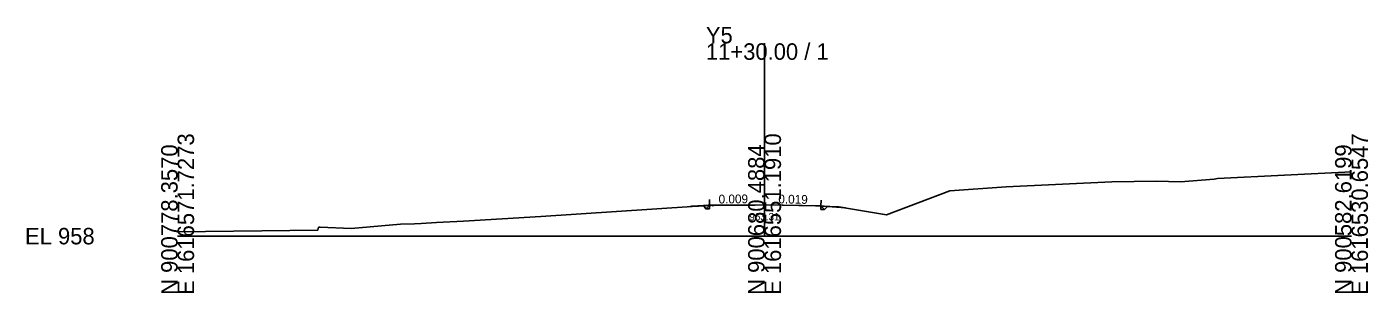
# Model space of a CAD drawing. Extents: x -26 to 1403, y -10 to 4517.
# Drawn here: x 1174.3 to 1402.8, y 490.3 to 535.6 of the extents above; entities that cross this region are included whole.
import ezdxf

# ---------------------------------------------------------------- set-up
doc = ezdxf.new("R2010")
doc.units = 0
for name, color, linetype in [('Exist Cross Section Cell', 7, 'Continuous'), ('Exist XS Center Line Elevation Label', 7, 'Continuous'), ('Exist XS Ground Line', 7, 'Continuous'), ('Prop XS Dump Level', 7, 'Continuous'), ('Prop XS Earthwork Shape', 7, 'Continuous'), ('Prop XS EOT Tick Mark', 7, 'Continuous'), ('Prop XS Finish Grade', 7, 'Continuous'), ('Prop XS Finish Grade Earthwork', 7, 'Continuous'), ('Prop XS Finish Grade Pavement', 7, 'Continuous'), ('Prop XS Pvmt Edge Slope', 7, 'Continuous'), ('Prop XS Subgrade Earthwork', 7, 'Continuous')]:
    doc.layers.add(name, color=color, linetype=linetype)

msp = doc.modelspace()

# ---------------------------------------------------------------- linework, layer by layer
at = {"layer": 'Exist Cross Section Cell'}
for p, q in [((1300, 500), (1300, 532.79)), ((1200, 500), (1300, 500)), ((1300, 500), (1400, 500))]:
    msp.add_line(p, q, dxfattribs=at)
at = {"layer": 'Exist XS Ground Line'}
for p, q in [((1370.85, 509.25), (1376.62, 509.67)), ((1376.62, 509.67), (1377.16, 509.8)), ((1377.16, 509.8), (1400, 510.93)), ((1320.75, 503.6), (1331.54, 507.68)), ((1331.54, 507.68), (1341.18, 508.38)), ((1341.18, 508.38), (1359.14, 509.23)), ((1359.14, 509.23), (1366.75, 509.32)), ((1366.75, 509.32), (1370.85, 509.25)), ((1287.69, 505.02), (1288.72, 505.07)), ((1288.72, 505.07), (1290.43, 505.24)), ((1290.43, 505.24), (1298.4, 505.27)), ((1298.4, 505.27), (1300.18, 505.32)), ((1300.18, 505.32), (1308.68, 505.16)), ((1308.68, 505.16), (1309.34, 505.14)), ((1309.34, 505.14), (1309.72, 505.12)), ((1309.72, 505.12), (1312.61, 505.01)), ((1248.72, 502.57), (1261.89, 503.35)), ((1261.89, 503.35), (1287.69, 505.02)), ((1312.61, 505.01), (1320.75, 503.6)), ((1200, 500.74), (1223.87, 500.99)), ((1223.87, 500.99), (1223.98, 501.51)), ((1223.98, 501.51), (1224.31, 501.5)), ((1224.31, 501.5), (1229.56, 501.32)), ((1229.56, 501.32), (1237.95, 502.02)), ((1237.95, 502.02), (1240.36, 502.07)), ((1240.36, 502.07), (1241.48, 502.15)), ((1241.48, 502.15), (1244.13, 502.34)), ((1244.13, 502.34), (1248.72, 502.57))]:
    msp.add_line(p, q, dxfattribs=at)
at = {"layer": 'Prop XS Dump Level'}
for p, q in [((1290.61, 505.23), (1300, 505.31)), ((1300, 505.31), (1309.61, 505.13))]:
    msp.add_line(p, q, dxfattribs=at)
at = {"layer": 'Prop XS Earthwork Shape'}
for points in [[(1287.04, 504.98), (1287.69, 505.02), (1288.72, 505.07), (1289.63, 505.16), (1289.61, 505.2), (1287.6, 505.12)], [(1290.61, 505.23), (1290.27, 505.22), (1289.63, 505.16), (1290.01, 504.63)], [(1290.61, 504.65), (1290.01, 504.63), (1290.61, 505.23)], [(1290.61, 505.23), (1290.27, 505.22), (1290.43, 505.24)], [(1309.61, 505.13), (1310.19, 504.55), (1310.71, 505.04)], [(1309.61, 505.13), (1310.19, 504.55), (1309.61, 504.55)], [(1309.61, 505.13), (1309.72, 505.12), (1312.61, 505.01), (1313.8, 504.8), (1310.71, 505.04)]]:
    msp.add_lwpolyline(points, close=True, dxfattribs=at)
at = {"layer": 'Prop XS EOT Tick Mark'}
for p, q in [((1290.61, 505.23), (1290.61, 506.23)), ((1309.61, 505.13), (1309.63, 506.13))]:
    msp.add_line(p, q, dxfattribs=at)
at = {"layer": 'Prop XS Finish Grade'}
for p, q in [((1290.61, 505.23), (1289.61, 505.2)), ((1309.61, 505.13), (1310.71, 505.04))]:
    msp.add_line(p, q, dxfattribs=at)
at = {"layer": 'Prop XS Finish Grade Earthwork'}
for p, q in [((1287.6, 505.12), (1287.04, 504.98)), ((1289.61, 505.19), (1287.6, 505.12)), ((1310.71, 505.04), (1313.8, 504.8))]:
    msp.add_line(p, q, dxfattribs=at)
at = {"layer": 'Prop XS Finish Grade Pavement'}
for p, q in [((1290.61, 505.23), (1300, 505.31)), ((1300, 505.31), (1309.61, 505.13))]:
    msp.add_line(p, q, dxfattribs=at)
at = {"layer": 'Prop XS Pvmt Edge Slope'}
for p, q in [((1290.61, 505.23), (1290.01, 504.63)), ((1309.61, 505.13), (1310.19, 504.55))]:
    msp.add_line(p, q, dxfattribs=at)
at = {"layer": 'Prop XS Subgrade Earthwork'}
for p, q in [((1290.01, 504.63), (1289.61, 505.2)), ((1290.61, 504.65), (1290.61, 505.24)), ((1309.61, 504.55), (1309.61, 505.13)), ((1290.61, 504.65), (1290.01, 504.63)), ((1309.61, 504.55), (1310.19, 504.55)), ((1310.71, 505.04), (1310.19, 504.55))]:
    msp.add_line(p, q, dxfattribs=at)

# ---------------------------------------------------------------- texts
at = {"layer": 'Exist Cross Section Cell'}
for s, p in [('Y5', (1290, 532.79)), ('11+30.00 / 1', (1290, 529.99)), ('EL 958', (1174, 498.6))]:
    msp.add_text(s, height=2.8, dxfattribs=at).set_placement(p)
for s, p in [('E 1616571.7273', (1202.8, 490)), ('E 1616551.1910', (1302.8, 490)), ('E 1616530.6547', (1402.8, 490)), ('N 900778.3570', (1200, 490)), ('N 900680.4884', (1300, 490)), ('N 900582.6199', (1400, 490))]:
    msp.add_text(s, height=2.8, rotation=90, dxfattribs=at).set_placement(p)
at = {"layer": 'Exist XS Center Line Elevation Label'}
msp.add_text('963.31', height=1.25, dxfattribs=at).set_placement((1297.42, 502.69))
at = {"layer": 'Prop XS Dump Level'}
msp.add_text('Eop', height=0.3, dxfattribs=at).set_placement((1290.61, 504.94))
at = {"layer": 'Prop XS Subgrade Earthwork'}
for s, rotation, p in [('0.009', 0.4755, (1292.17, 505.55)), ('0.019', 358.9155, (1302.33, 505.57))]:
    msp.add_text(s, height=1.5, rotation=rotation, dxfattribs=at).set_placement(p)

doc.saveas('drawing.dxf')
